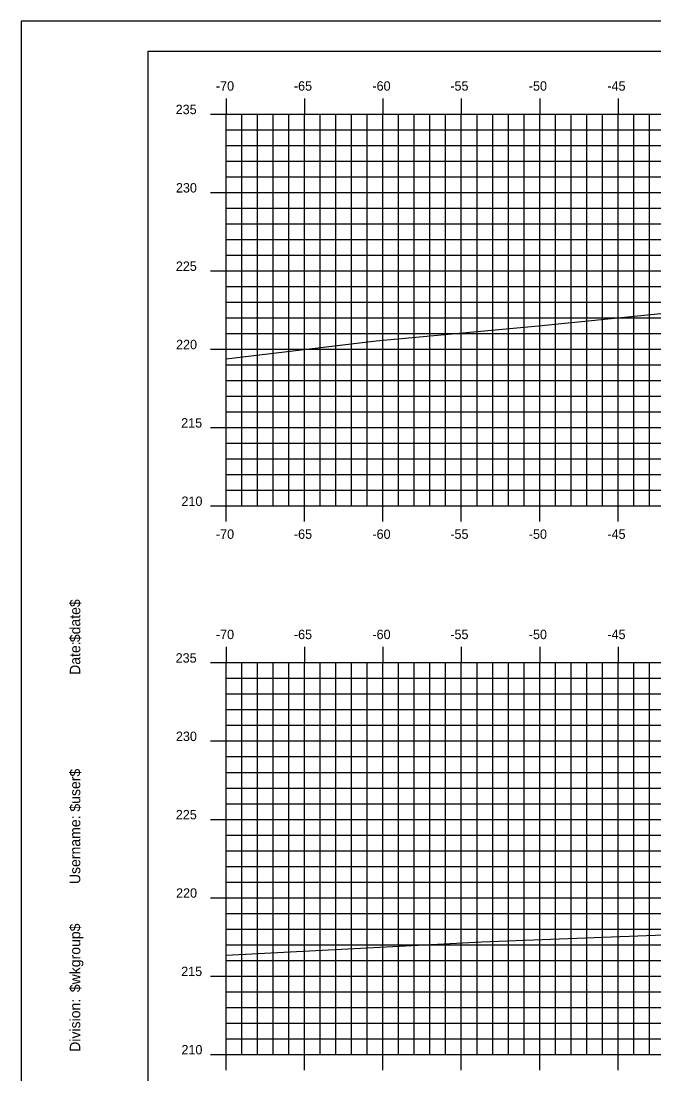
# Model space of a CAD drawing. Extents: x 1137654 to 1137824, y 608981 to 609091.
# Drawn here: x 1137654.3 to 1137694.7, y 609024.1 to 609091.3 of the extents above; entities that cross this region are included whole.
import ezdxf

# ---------------------------------------------------------------- set-up
doc = ezdxf.new("R2010")
doc.units = 0
for name, color, linetype in [('BORDER', 7, 'Continuous'), ('H_V ANNOTATION', 7, 'Continuous'), ('MAJOR', 7, 'Continuous'), ('MINOR', 7, 'Continuous'), ('PLOT BOUNDARY', 7, 'Continuous'), ('S_Roadway_Centerline', 7, 'Continuous')]:
    doc.layers.add(name, color=color, linetype=linetype)

msp = doc.modelspace()

# ---------------------------------------------------------------- linework, layer by layer
at = {"layer": 'BORDER'}
msp.add_lwpolyline([(1137662.41, 608984.335), (1137822.41, 608984.335), (1137822.41, 609089.335), (1137662.41, 609089.335)], close=True, dxfattribs=at)
at = {"layer": 'MAJOR'}
for p, q in [((1137667.409, 609086.337), (1137667.409, 609085.335)), ((1137672.409, 609086.337), (1137672.409, 609085.335)), ((1137677.409, 609086.337), (1137677.409, 609085.335)), ((1137682.409, 609086.337), (1137682.409, 609085.335)), ((1137687.409, 609086.337), (1137687.409, 609085.335)), ((1137692.409, 609086.337), (1137692.409, 609085.335)), ((1137666.407, 609085.335), (1137667.409, 609085.335)), ((1137667.409, 609085.335), (1137807.409, 609085.335)), ((1137667.409, 609060.335), (1137667.409, 609085.335)), ((1137667.409, 609060.335), (1137667.409, 609085.335)), ((1137667.409, 609085.335), (1137807.409, 609085.335)), ((1137672.409, 609060.335), (1137672.409, 609085.335)), ((1137677.409, 609060.335), (1137677.409, 609085.335)), ((1137682.409, 609060.335), (1137682.409, 609085.335)), ((1137687.409, 609060.335), (1137687.409, 609085.335)), ((1137692.409, 609060.335), (1137692.409, 609085.335)), ((1137666.407, 609080.335), (1137667.409, 609080.335)), ((1137667.409, 609080.335), (1137807.409, 609080.335)), ((1137666.407, 609075.335), (1137667.409, 609075.335)), ((1137667.409, 609075.335), (1137807.409, 609075.335)), ((1137666.407, 609070.335), (1137667.409, 609070.335)), ((1137667.409, 609070.335), (1137807.409, 609070.335)), ((1137666.407, 609065.335), (1137667.409, 609065.335)), ((1137667.409, 609065.335), (1137807.409, 609065.335)), ((1137666.407, 609060.335), (1137667.409, 609060.335)), ((1137667.409, 609060.335), (1137807.409, 609060.335)), ((1137667.409, 609060.335), (1137807.409, 609060.335)), ((1137667.409, 609059.333), (1137667.409, 609060.335)), ((1137672.409, 609059.333), (1137672.409, 609060.335)), ((1137677.409, 609059.333), (1137677.409, 609060.335)), ((1137682.409, 609059.333), (1137682.409, 609060.335)), ((1137687.409, 609059.333), (1137687.409, 609060.335)), ((1137692.409, 609059.333), (1137692.409, 609060.335)), ((1137667.409, 609051.337), (1137667.409, 609050.335)), ((1137672.409, 609051.337), (1137672.409, 609050.335)), ((1137677.409, 609051.337), (1137677.409, 609050.335)), ((1137682.409, 609051.337), (1137682.409, 609050.335)), ((1137687.409, 609051.337), (1137687.409, 609050.335)), ((1137692.409, 609051.337), (1137692.409, 609050.335)), ((1137666.407, 609050.335), (1137667.409, 609050.335)), ((1137667.409, 609050.335), (1137807.409, 609050.335)), ((1137667.409, 609025.335), (1137667.409, 609050.335)), ((1137667.409, 609025.335), (1137667.409, 609050.335)), ((1137667.409, 609050.335), (1137807.409, 609050.335)), ((1137672.409, 609025.335), (1137672.409, 609050.335)), ((1137677.409, 609025.335), (1137677.409, 609050.335)), ((1137682.409, 609025.335), (1137682.409, 609050.335)), ((1137687.409, 609025.335), (1137687.409, 609050.335)), ((1137692.409, 609025.335), (1137692.409, 609050.335)), ((1137666.407, 609045.335), (1137667.409, 609045.335)), ((1137667.409, 609045.335), (1137807.409, 609045.335)), ((1137666.407, 609040.335), (1137667.409, 609040.335)), ((1137667.409, 609040.335), (1137807.409, 609040.335)), ((1137666.407, 609035.335), (1137667.409, 609035.335)), ((1137667.409, 609035.335), (1137807.409, 609035.335)), ((1137666.407, 609030.335), (1137667.409, 609030.335)), ((1137667.409, 609030.335), (1137807.409, 609030.335)), ((1137666.407, 609025.335), (1137667.409, 609025.335)), ((1137667.409, 609025.335), (1137807.409, 609025.335)), ((1137667.409, 609025.335), (1137807.409, 609025.335)), ((1137667.409, 609024.333), (1137667.409, 609025.335)), ((1137672.409, 609024.333), (1137672.409, 609025.335)), ((1137677.409, 609024.333), (1137677.409, 609025.335)), ((1137682.409, 609024.333), (1137682.409, 609025.335)), ((1137687.409, 609024.333), (1137687.409, 609025.335)), ((1137692.409, 609024.333), (1137692.409, 609025.335))]:
    msp.add_line(p, q, dxfattribs=at)
at = {"layer": 'MINOR'}
for p, q in [((1137668.409, 609060.335), (1137668.409, 609085.335)), ((1137669.409, 609060.335), (1137669.409, 609085.335)), ((1137670.409, 609060.335), (1137670.409, 609085.335)), ((1137671.409, 609060.335), (1137671.409, 609085.335)), ((1137673.409, 609060.335), (1137673.409, 609085.335)), ((1137674.409, 609060.335), (1137674.409, 609085.335)), ((1137675.409, 609060.335), (1137675.409, 609085.335)), ((1137676.409, 609060.335), (1137676.409, 609085.335)), ((1137678.409, 609060.335), (1137678.409, 609085.335)), ((1137679.409, 609060.335), (1137679.409, 609085.335)), ((1137680.409, 609060.335), (1137680.409, 609085.335)), ((1137681.409, 609060.335), (1137681.409, 609085.335)), ((1137683.409, 609060.335), (1137683.409, 609085.335)), ((1137684.409, 609060.335), (1137684.409, 609085.335)), ((1137685.409, 609060.335), (1137685.409, 609085.335)), ((1137686.409, 609060.335), (1137686.409, 609085.335)), ((1137688.409, 609060.335), (1137688.409, 609085.335)), ((1137689.409, 609060.335), (1137689.409, 609085.335)), ((1137690.409, 609060.335), (1137690.409, 609085.335)), ((1137691.409, 609060.335), (1137691.409, 609085.335)), ((1137693.409, 609060.335), (1137693.409, 609085.335)), ((1137694.409, 609060.335), (1137694.409, 609085.335)), ((1137667.409, 609084.335), (1137807.409, 609084.335)), ((1137667.409, 609084.335), (1137668.411, 609084.335)), ((1137667.409, 609083.335), (1137807.409, 609083.335)), ((1137667.409, 609083.335), (1137668.411, 609083.335)), ((1137667.409, 609082.335), (1137807.409, 609082.335)), ((1137667.409, 609082.335), (1137668.411, 609082.335)), ((1137667.409, 609081.335), (1137807.409, 609081.335)), ((1137667.409, 609081.335), (1137668.411, 609081.335)), ((1137667.409, 609079.335), (1137807.409, 609079.335)), ((1137667.409, 609079.335), (1137668.411, 609079.335)), ((1137667.409, 609078.335), (1137807.409, 609078.335)), ((1137667.409, 609078.335), (1137668.411, 609078.335)), ((1137667.409, 609077.335), (1137807.409, 609077.335)), ((1137667.409, 609077.335), (1137668.411, 609077.335)), ((1137667.409, 609076.335), (1137807.409, 609076.335)), ((1137667.409, 609076.335), (1137668.411, 609076.335)), ((1137667.409, 609074.335), (1137807.409, 609074.335)), ((1137667.409, 609074.335), (1137668.411, 609074.335)), ((1137667.409, 609073.335), (1137807.409, 609073.335)), ((1137667.409, 609073.335), (1137668.411, 609073.335)), ((1137667.409, 609072.335), (1137807.409, 609072.335)), ((1137667.409, 609072.335), (1137668.411, 609072.335)), ((1137667.409, 609071.335), (1137807.409, 609071.335)), ((1137667.409, 609071.335), (1137668.411, 609071.335)), ((1137667.409, 609069.335), (1137807.409, 609069.335)), ((1137667.409, 609069.335), (1137668.411, 609069.335)), ((1137667.409, 609068.335), (1137807.409, 609068.335)), ((1137667.409, 609068.335), (1137668.411, 609068.335)), ((1137667.409, 609067.335), (1137807.409, 609067.335)), ((1137667.409, 609067.335), (1137668.411, 609067.335)), ((1137667.409, 609066.335), (1137807.409, 609066.335)), ((1137667.409, 609066.335), (1137668.411, 609066.335)), ((1137667.409, 609064.335), (1137807.409, 609064.335)), ((1137667.409, 609064.335), (1137668.411, 609064.335)), ((1137667.409, 609063.335), (1137807.409, 609063.335)), ((1137667.409, 609063.335), (1137668.411, 609063.335)), ((1137667.409, 609062.335), (1137807.409, 609062.335)), ((1137667.409, 609062.335), (1137668.411, 609062.335)), ((1137667.409, 609061.335), (1137807.409, 609061.335)), ((1137667.409, 609061.335), (1137668.411, 609061.335)), ((1137668.409, 609025.335), (1137668.409, 609050.335)), ((1137669.409, 609025.335), (1137669.409, 609050.335)), ((1137670.409, 609025.335), (1137670.409, 609050.335)), ((1137671.409, 609025.335), (1137671.409, 609050.335)), ((1137673.409, 609025.335), (1137673.409, 609050.335)), ((1137674.409, 609025.335), (1137674.409, 609050.335)), ((1137675.409, 609025.335), (1137675.409, 609050.335)), ((1137676.409, 609025.335), (1137676.409, 609050.335)), ((1137678.409, 609025.335), (1137678.409, 609050.335)), ((1137679.409, 609025.335), (1137679.409, 609050.335)), ((1137680.409, 609025.335), (1137680.409, 609050.335)), ((1137681.409, 609025.335), (1137681.409, 609050.335)), ((1137683.409, 609025.335), (1137683.409, 609050.335)), ((1137684.409, 609025.335), (1137684.409, 609050.335)), ((1137685.409, 609025.335), (1137685.409, 609050.335)), ((1137686.409, 609025.335), (1137686.409, 609050.335)), ((1137688.409, 609025.335), (1137688.409, 609050.335)), ((1137689.409, 609025.335), (1137689.409, 609050.335)), ((1137690.409, 609025.335), (1137690.409, 609050.335)), ((1137691.409, 609025.335), (1137691.409, 609050.335)), ((1137693.409, 609025.335), (1137693.409, 609050.335)), ((1137694.409, 609025.335), (1137694.409, 609050.335)), ((1137667.409, 609049.335), (1137807.409, 609049.335)), ((1137667.409, 609049.335), (1137668.411, 609049.335)), ((1137667.409, 609048.335), (1137807.409, 609048.335)), ((1137667.409, 609048.335), (1137668.411, 609048.335)), ((1137667.409, 609047.335), (1137807.409, 609047.335)), ((1137667.409, 609047.335), (1137668.411, 609047.335)), ((1137667.409, 609046.335), (1137807.409, 609046.335)), ((1137667.409, 609046.335), (1137668.411, 609046.335)), ((1137667.409, 609044.335), (1137807.409, 609044.335)), ((1137667.409, 609044.335), (1137668.411, 609044.335)), ((1137667.409, 609043.335), (1137807.409, 609043.335)), ((1137667.409, 609043.335), (1137668.411, 609043.335)), ((1137667.409, 609042.335), (1137807.409, 609042.335)), ((1137667.409, 609042.335), (1137668.411, 609042.335)), ((1137667.409, 609041.335), (1137807.409, 609041.335)), ((1137667.409, 609041.335), (1137668.411, 609041.335)), ((1137667.409, 609039.335), (1137807.409, 609039.335)), ((1137667.409, 609039.335), (1137668.411, 609039.335)), ((1137667.409, 609038.335), (1137807.409, 609038.335)), ((1137667.409, 609038.335), (1137668.411, 609038.335)), ((1137667.409, 609037.335), (1137807.409, 609037.335)), ((1137667.409, 609037.335), (1137668.411, 609037.335)), ((1137667.409, 609036.335), (1137807.409, 609036.335)), ((1137667.409, 609036.335), (1137668.411, 609036.335)), ((1137667.409, 609034.335), (1137807.409, 609034.335)), ((1137667.409, 609034.335), (1137668.411, 609034.335)), ((1137667.409, 609033.335), (1137807.409, 609033.335)), ((1137667.409, 609033.335), (1137668.411, 609033.335)), ((1137667.409, 609032.335), (1137807.409, 609032.335)), ((1137667.409, 609032.335), (1137668.411, 609032.335)), ((1137667.409, 609031.335), (1137807.409, 609031.335)), ((1137667.409, 609031.335), (1137668.411, 609031.335)), ((1137667.409, 609029.335), (1137807.409, 609029.335)), ((1137667.409, 609029.335), (1137668.411, 609029.335)), ((1137667.409, 609028.335), (1137807.409, 609028.335)), ((1137667.409, 609028.335), (1137668.411, 609028.335)), ((1137667.409, 609027.335), (1137807.409, 609027.335)), ((1137667.409, 609027.335), (1137668.411, 609027.335)), ((1137667.409, 609026.335), (1137807.409, 609026.335)), ((1137667.409, 609026.335), (1137668.411, 609026.335))]:
    msp.add_line(p, q, dxfattribs=at)
at = {"layer": 'PLOT BOUNDARY'}
msp.add_lwpolyline([(1137654.316, 608981.276), (1137824.316, 608981.276), (1137824.316, 609091.276), (1137654.316, 609091.276)], close=True, dxfattribs=at)
at = {"layer": 'S_Roadway_Centerline'}
for points in [[(1137667.409, 609069.72), (1137676.984, 609070.875), (1137687.338, 609071.833), (1137697.235, 609072.821), (1137703.411, 609073.206), (1137707.864, 609073.49), (1137714.699, 609072.26), (1137721.151, 609073.928), (1137723.806, 609074.396), (1137725.924, 609074.671), (1137726.331, 609074.705), (1137728.139, 609074.727), (1137737.517, 609074.967), (1137739.695, 609074.987), (1137747.943, 609075.052), (1137748.455, 609075.015), (1137749.9, 609074.851), (1137752.206, 609074.198), (1137752.624, 609074.067), (1137753.307, 609074.115), (1137755.515, 609074.146), (1137758.076, 609075.005), (1137759.89, 609075.513), (1137770.942, 609076.182)], [(1137667.409, 609031.673), (1137680.898, 609032.377), (1137683.689, 609032.524), (1137701.957, 609033.219), (1137704.697, 609033.873), (1137715.818, 609036.339), (1137722.54, 609039.054), (1137724.51, 609039.355), (1137725.115, 609039.434), (1137727.86, 609039.504), (1137736.081, 609039.689), (1137744.308, 609039.789), (1137746.709, 609039.808), (1137746.997, 609039.677), (1137753.261, 609039.323), (1137761.612, 609039.363), (1137761.894, 609039.317), (1137766.806, 609039.577), (1137782.426, 609039.995), (1137793.11, 609040.238), (1137799.729, 609040.508), (1137807.409, 609040.788)]]:
    msp.add_lwpolyline(points, dxfattribs=at)

# ---------------------------------------------------------------- texts
at = {"layer": 'BORDER'}
for s, p in [('$date$', (1137658.095, 609051.64)), ('Date:', (1137658.095, 609049.552)), ('$user$', (1137658.095, 609040.827)), ('Username:', (1137658.095, 609036.203)), ('$wkgroup$', (1137658.095, 609029.305)), ('Division:', (1137658.095, 609025.501))]:
    msp.add_text(s, height=0.6696, rotation=90, dxfattribs=at).set_placement(p)
at = {"layer": 'H_V ANNOTATION'}
for s, p in [('-70', (1137666.751, 609086.835)), ('-65', (1137671.727, 609086.835)), ('-60', (1137676.735, 609086.835)), ('-55', (1137681.706, 609086.835)), ('-50', (1137686.714, 609086.835)), ('-45', (1137691.727, 609086.835)), ('235', (1137664.181, 609085.335)), ('230', (1137664.197, 609080.335)), ('225', (1137664.191, 609075.335)), ('220', (1137664.207, 609070.335)), ('215', (1137664.534, 609065.335)), ('210', (1137664.55, 609060.335)), ('-70', (1137666.751, 609058.235)), ('-65', (1137671.727, 609058.235)), ('-60', (1137676.735, 609058.235)), ('-55', (1137681.706, 609058.235)), ('-50', (1137686.714, 609058.235)), ('-45', (1137691.727, 609058.235)), ('-70', (1137666.751, 609051.835)), ('-65', (1137671.727, 609051.835)), ('-60', (1137676.735, 609051.835)), ('-55', (1137681.706, 609051.835)), ('-50', (1137686.714, 609051.835)), ('-45', (1137691.727, 609051.835)), ('235', (1137664.181, 609050.335)), ('230', (1137664.197, 609045.335)), ('225', (1137664.191, 609040.335)), ('220', (1137664.207, 609035.335)), ('215', (1137664.534, 609030.335)), ('210', (1137664.55, 609025.335))]:
    msp.add_text(s, height=0.6, dxfattribs=at).set_placement(p)
at = {"layer": 'MAJOR'}
for p in [(1137667.405, 609060.335), (1137667.405, 609025.335)]:
    msp.add_text('-', height=0.006, dxfattribs=at).set_placement(p)

doc.saveas('drawing.dxf')
